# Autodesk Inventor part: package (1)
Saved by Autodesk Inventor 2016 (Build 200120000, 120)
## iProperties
Created: 2016-09
Part Number: package (1)
Material: Generic
Document SubType Name: Modeling
Designer: Administrator
Appearance: Generic
Author: Administrator
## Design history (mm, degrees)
feature "Body1"
body "Solid1"
